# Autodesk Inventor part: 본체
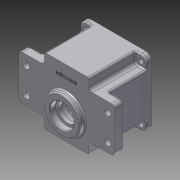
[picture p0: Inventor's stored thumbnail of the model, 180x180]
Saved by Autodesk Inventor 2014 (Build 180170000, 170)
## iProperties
Created: 2015-07
Part Number: 본체
Material: 알루미늄 6061
Document SubType Name: Modeling
Designer: Administrator
Density: 2.71 g/cm^3
Appearance: 알루미늄 - 평지
Mass: 705.361 g
Surface Area: 672.962 cm^2
Volume: 260.281 cm^3
Author: Administrator
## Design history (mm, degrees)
sketch "스케치1"
  geometry: L1 (45, 45)-(-45, 45); L2 (-45, 45)-(-45, -45); L3 (-45, -45)-(45, -45); L4 (45, -45)-(45, 45); L5 (45, 45)-(-45, -45); L6 (-45, 45)-(45, -45); 1 further point
  constraints: 12 end point, 2 midpoint, 2 parallel, 1 horizontal, 1 perpendicular
  dimensions: "d0" = 90 distance of L3.end L2.end; "d1" = 90 distance of L2.end L1.end
extrude "돌출1" new body sketch "스케치1" distance "d2" = 70; taper "d3" = 0 deg
sketch "스케치3"
  geometry: L1 (-65, 30)-(65, 30); L2 (65, 30)-(65, -30); L3 (65, -30)-(-65, -30); L4 (-65, -30)-(-65, 30); L5 (-65, 30)-(65, -30); L6 (65, 30)-(-65, -30); 1 further point
  constraints: 12 end point, 2 midpoint, 2 parallel, 1 horizontal, 1 perpendicular
  dimensions: "d8" = 130 distance of L2.end L3.end; "d9" = 60 distance of L1.end L2.end
extrude "돌출3" join sketch "스케치3" distance "d10" = 12; taper "d11" = 0 deg
sketch "스케치4"
  geometry: L1 (65, -30)-(45, -30) reference; L2 (45, 30)-(65, 30) reference; L3 (-65, 30)-(-45, 30) reference; L4 (-45, -30)-(-65, -30) reference; L5 (-45, 45)-(-30, 45); L6 (-30, 45)-(-30, 30); L7 (-30, 30)-(-45, 30); L8 (-45, 30)-(-45, 45); L9 (45, 45)-(30, 45); L10 (30, 45)-(30, 30); L11 (30, 30)-(45, 30); L12 (45, 30)-(45, 45); L13 (-45, -45)-(-30, -45); L14 (-30, -45)-(-30, -30); L15 (-30, -30)-(-45, -30); L16 (-45, -30)-(-45, -45); L17 (45, -45)-(30, -45); L18 (30, -45)-(30, -30); L19 (30, -30)-(45, -30); L20 (45, -30)-(45, -45); 1 further point
  constraints: 32 end point, 8 parallel, 4 horizontal, 4 perpendicular, 3 collinear, 1 point on line
  dimensions: "d12" = 60 distance between parallel lines of L18 L14; "d13" = 60 distance between parallel lines of L10 L6; "d14" = 30 distance from line of L14 point (0, 0); "d15" = 30 distance from line of L6 point (0, 0)
extrude "돌출4" cut sketch "스케치4" distance "d16" = 63; taper "d17" = 0 deg
fillet "모깎기1" dims "d18" = 5
fillet "모깎기2" dims "d19" = 8
fillet "모깎기3" dims "d20" = 5
sketch "스케치5"
  geometry: L1 (37, -45)-(-37, -45) reference; L2 (-45, -37)-(-45, 37) reference; L3 (-37, 45)-(37, 45) reference; L4 (45, 37)-(45, -37) reference; C1 r 3.5 at (37, 37); C2 r 3.5 at (-37, 37); C3 r 3.5 at (37, -37); C4 r 3.5 at (-37, -37); A1 r 8 centre (37, -37) between (37, -45) and (45, -37) reference; A2 r 8 centre (-37, -37) between (-45, -37) and (-37, -45) reference; A3 r 8 centre (-37, 37) between (-37, 45) and (-45, 37) reference; A4 r 8 centre (37, 37) between (45, 37) and (37, 45) reference; 1 further point
  constraints: 4 centre point, 4 coincident
  dimensions: "d21" = 7 diameter of C1; "d22" = 7 diameter of C2; "d23" = 7 diameter of C3; "d24" = 7 diameter of C4
extrude "돌출5" cut sketch "스케치5" stored distance "d25" = 63; taper "d26" = 0 deg
sketch "스케치6"
  geometry: C1 r 4.5 at (-55, 17.5); C2 r 4.5 at (-55, -17.5); C3 r 4.5 at (55, -17.5); C4 r 4.5 at (55, 17.5); 1 further point
  constraints: 4 centre point, 2 horizontal alignment, 2 vertical alignment
  dimensions: "d27" = 9 diameter of C1; "d28" = 9 diameter of C2; "d29" = 9 diameter of C3; "d30" = 9 diameter of C4; "d31" = 35 distance of C3.centre C4.centre; "d32" = 110 distance of C4.centre C1.centre; "d33" = 17.5 vertical distance of C4.centre point (0, 0); "d34" = 55 horizontal distance of point (0, 0) C2.centre
extrude "돌출6" cut sketch "스케치6" stored distance "d35" = 63; taper "d36" = 0 deg
sketch "스케치7"
  geometry: C1 r 40 at (0, 0); 1 further point
  constraints: 1 centre point, 1 coincident
  dimensions: "d37" = 80 diameter of C1
extrude "돌출7" cut sketch "스케치7" distance "d38" = 9; taper "d39" = 0 deg
sketch "스케치8"
  geometry: C1 r 40 at (0, 0) reference; C2 r 39 at (0, 0)
  constraints: 1 centre point, 1 coincident
  dimensions: "d40" = 78 diameter of C2
extrude "돌출8" cut sketch "스케치8" distance "d41" = 52; taper "d42" = 0 deg
sketch "스케치10"
  geometry: C1 r 39 at (0, 0) reference; C2 r 20.5 at (0, 11); C3 r 14 at (0, -20)
  constraints: 2 centre point, 2 vertical alignment
  dimensions: "d50" = 41 diameter of C2; "d51" = 11 distance of C1.centre C2.centre; "d52" = 28 diameter of C3; "d53" = 20 distance of C3.centre C1.centre
extrude "돌출9" join sketch "스케치10" distance "d54" = 7; taper "d55" = 0 deg
sketch "스케치11"
  geometry: C1 r 17.5 at (0, 11); A1 r 20.5 centre (0, 11) between (7.402, -8.117) and (-7.402, -8.117) reference; 1 further point
  constraints: 1 centre point, 1 coincident
  dimensions: "d56" = 35 diameter of C1
extrude "돌출10" cut sketch "스케치11" distance "d57" = 10; taper "d58" = 0 deg
sketch "스케치12"
  geometry: C1 r 17.5 at (0, -11) reference; C2 r 25 at (0, -11); 1 further point
  constraints: 1 centre point, 1 coincident
  dimensions: "d59" = 50 diameter of C2
extrude "돌출11" join sketch "스케치12" distance "d60" = 7; taper "d61" = 0 deg
sketch "스케치13"
  geometry: C1 r 25 at (0, 0) reference; C2 r 16 at (0, 0); 1 further point
  constraints: 1 centre point, 1 coincident
  dimensions: "d62" = 32 diameter of C2
extrude "돌출12" cut sketch "스케치13" distance "d63" = 8; taper "d64" = 0 deg
sketch "스케치14"
  geometry: C1 r 16 at (0, 0) reference; C2 r 12.5 at (0, 0); 1 further point
  constraints: 1 centre point, 1 coincident
  dimensions: "d65" = 25 diameter of C2
extrude "돌출13" cut sketch "스케치14" stored distance "d66" = 10; taper "d67" = 0 deg
sketch "스케치15"
  geometry: C1 r 11 at (0, -20); A1 r 14 centre (0, -20) between (-7.402, -8.117) and (7.402, -8.117) reference; 1 further point
  constraints: 1 centre point, 1 coincident
  dimensions: "d68" = 22 diameter of C1
extrude "돌출14" cut sketch "스케치15" distance "d69" = 7; taper "d70" = 0 deg
sketch "스케치16"
  geometry: C1 r 11 at (0, 0) reference; C2 r 9.5 at (0, 0); 1 further point
  constraints: 1 centre point, 1 coincident
  dimensions: "d71" = 19 diameter of C2
extrude "돌출15" cut sketch "스케치16" distance "d72" = 1; taper "d73" = 0 deg
sketch "스케치17"
  geometry: L1 (0, 0)-(35, 0); L2 (-27.577, -27.577)-(27.577, 27.577); L3 (-27.577, 27.577)-(27.577, -27.577); L4 (27.577, 27.577)-(24.749, 24.749); L5 (24.749, 30.406)-(21.92, 27.577); L6 (27.577, 21.92)-(30.406, 24.749); A1 r 39 centre (0, 0) between (-27.577, -27.577) and (27.577, 27.577) reference; A2 r 35 centre (0, 0) between (35, 0) and (24.749, 24.749); A3 r 4 centre (27.577, 27.577) between (30.406, 24.749) and (24.749, 30.406); A4 r 4 centre (24.749, 24.749) between (21.92, 27.577) and (27.577, 21.92); 1 further point
  constraints: 14 end point, 10 point on circle, 4 tangent, 3 centre point, 3 midpoint, 1 coincident, 1 horizontal, 1 parallel, 1 point on line
  dimensions: "d74" = 70 diameter of A2; "d75" = 45 deg angle of L1 L2; "d76" = 90 deg angle of L2 L3; "d77" = 4 radius of A4
extrude "돌출16" join sketch "스케치17" stored distance "d78" = 10; taper "d79" = 0 deg
sketch "스케치18"
  geometry: A1 r 4 centre (-24.749, -24.749) between (-21.92, -27.577) and (-27.577, -21.92) reference; A2 r 4 centre (-24.749, 24.749) between (-27.577, 21.92) and (-21.92, 27.577) reference; A3 r 4 centre (24.749, 24.749) between (21.92, 27.577) and (27.577, 21.92) reference; A4 r 4 centre (24.749, -24.749) between (27.577, -21.92) and (21.92, -27.577) reference
hole "구멍1" sketch "스케치18" at (-24.749, 24.749), (-24.749, -24.749), (24.749, -24.749), (24.749, 24.749) diameter "d83" = 3.459; stored, may be unused: countersink angle "d87" = 90 deg, drill point angle "d89" = 118 deg; dims "d84" = 12, "d85" = 4, "d86" = 2, "d88" = 15
sketch "스케치19"
  geometry: L1 (30, 45)-(-30, 45) reference; C1 r 25 at (0, -11) reference; 2 further points
  constraints: 1 vertical alignment, 1 other
  dimensions: "d90" = 15 distance from line of L1 point (0, 30)
feature "엠보싱1" sketch "스케치19" dims "d0" = 90, "d1" = 90, "d91" = 0.5, "d92" = 0
fillet "모깎기4" dims "d93" = 3.5
fillet "모깎기5" dims "d94" = 3
fillet "모깎기6" dims "d95" = 0.3
chamfer "모따기1" distance "d96" = 1; stored, may be unused: second distance "d97" = 2, angle "d98" = 45 deg
fillet "모깎기7" dims "d99" = 2
fillet "모깎기8" dims "d100" = 2
fillet "모깎기9" dims "d101" = 2
fillet "모깎기10" dims "d102" = 2
node "솔리드1"
pattern_circular "원형 패턴1" dims angle "d81" = 360 deg
node "투영된 루프1"
node "투영된 루프2"
